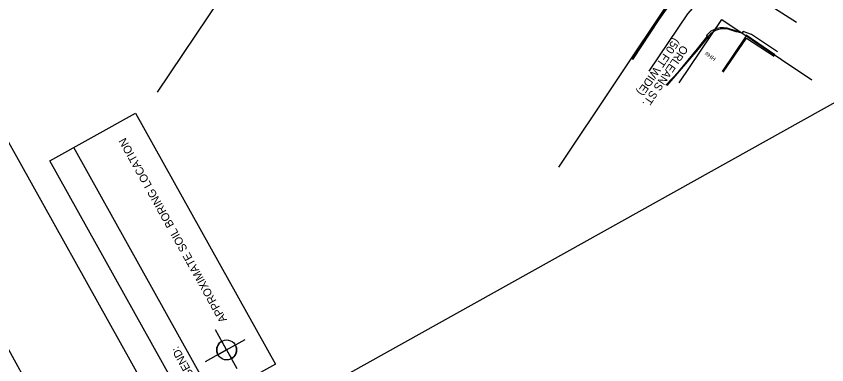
# Model space of a CAD drawing. Extents: x 13482447 to 13495412, y 324533 to 340229.
# Drawn here: x 13493140.7 to 13493623.3, y 331592.4 to 331799.7 of the extents above; entities that cross this region are included whole.
import ezdxf

# ---------------------------------------------------------------- set-up
doc = ezdxf.new("R2010")
doc.units = 0
for name, color, linetype in [('BORDER', 7, 'Continuous'), ('Default', 7, 'Continuous'), ('Level 1', 7, 'Continuous'), ('TYPICAL_TEXT_DIMEN_PR', 7, 'Continuous'), ('V-ANNO-TEXT', 7, 'Continuous'), ('V-BLDG-OTLN', 7, 'Continuous'), ('V-PROP-RWAY', 7, 'Continuous'), ('V-PVMT-BACK', 7, 'Continuous'), ('V-PVMT-CNTR', 7, 'Continuous'), ('V-PVMT-ROAD', 7, 'Continuous'), ('V-TOPO-IDEN', 7, 'Continuous')]:
    doc.layers.add(name, color=color, linetype=linetype)

msp = doc.modelspace()

# ---------------------------------------------------------------- linework, layer by layer
at = {"layer": 'Default'}
msp.add_lwpolyline([(13493738.83, 331810.18), (13493240.94, 331532.61)], dxfattribs=at)
at = {"layer": 'Level 1'}
for p, q in [((13493612.91, 330747.03), (13492913.2, 332001.03)), ((13493636.07, 330828.66), (13492994.84, 331977.87))]:
    msp.add_line(p, q, dxfattribs=at)
at = {"layer": 'TYPICAL_TEXT_DIMEN_PR'}
for p, q in [((13493258.89, 331571.46), (13493175.09, 331721.64)), ((13493265.99, 331601.22), (13493259.28, 331613.24)), ((13493265.99, 331601.22), (13493277, 331607.36)), ((13493265.99, 331601.22), (13493253.28, 331594.12)), ((13493265.99, 331601.22), (13493272.14, 331590.21))]:
    msp.add_line(p, q, dxfattribs=at)
msp.add_lwpolyline([(13493244.14, 331564.28), (13493160.79, 331713.66), (13493211.64, 331742.04), (13493295, 331592.65)], close=True, dxfattribs=at)
for points in [[(13493260.8, 331598.32), (13493265.99, 331601.22), (13493263.1, 331606.41)], [(13493271.18, 331604.11), (13493265.99, 331601.22), (13493268.89, 331596.03)]]:
    msp.add_lwpolyline(points, dxfattribs=at)
msp.add_circle((13493265.99, 331601.22), 5.94, dxfattribs=at)
for start, end in [(119.1605, 209.1605), (299.1605, 29.1605)]:
    msp.add_arc((13493265.99, 331601.22), 5.94, start, end, dxfattribs=at)
at = {"layer": 'V-BLDG-OTLN'}
for points in [[(13493592.42, 331776.73), (13493575.34, 331788.01), (13493561.02, 331766.8)], [(13493561.61, 331766.39), (13493575.55, 331786.74), (13493591.93, 331776)]]:
    msp.add_lwpolyline(points, dxfattribs=at)
at = {"layer": 'V-PROP-RWAY'}
for p, q in [((13493477.23, 332131.7), (13493224.66, 331754.53)), ((13493534, 331815.23), (13493463.52, 331709.94)), ((13493535.54, 331760.01), (13493560.86, 331797.83)), ((13493560.86, 331797.83), (13493614.45, 331761.96))]:
    msp.add_line(p, q, dxfattribs=at)
at = {"layer": 'V-PVMT-BACK'}
for points in [[(13493507.69, 331774.06), (13493523.14, 331797.99), (13493526.58, 331803.26), (13493531.99, 331810.53), (13493532.93, 331811.94), (13493533.5, 331813.14), (13493533.78, 331814.45), (13493533.73, 331815.79), (13493533.37, 331817.08), (13493532.71, 331818.25), (13493531.8, 331819.23), (13493531.23, 331819.64)], [(13493570.06, 331790.34), (13493569.44, 331790.51), (13493565.29, 331791.74), (13493564.57, 331791.94), (13493562.69, 331792.23), (13493560.79, 331792.2), (13493558.92, 331791.86), (13493557.13, 331791.21), (13493555.48, 331790.27), (13493554.01, 331789.06), (13493552.76, 331787.63), (13493552.7, 331787.55), (13493546.63, 331779.82), (13493528.01, 331758.48)]]:
    msp.add_lwpolyline(points, dxfattribs=at)
at = {"layer": 'V-PVMT-CNTR'}
for points in [[(13493605.37, 331796), (13493578.55, 331813.26), (13493565.46, 331822.12), (13493559.01, 331826.3), (13493554.28, 331829.11), (13493520.81, 331851.15), (13493485.5, 331874.76), (13493449.91, 331898.35), (13493414.95, 331921.85), (13493381.07, 331944.31), (13493362.78, 331957.08), (13493333.61, 331976.1), (13493307.04, 331993.94), (13493274.45, 332015.96), (13493240.12, 332038.89), (13493207.02, 332061.34), (13493179.15, 332079.98)], [(13493600.67, 331886.67), (13493578.69, 331854.34), (13493559.01, 331826.3), (13493547.8, 331809.65), (13493540.48, 331801.21), (13493517.42, 331767.01)]]:
    msp.add_lwpolyline(points, dxfattribs=at)
at = {"layer": 'V-PVMT-ROAD'}
for points in [[(13493507.76, 331774.02), (13493523.6, 331797.69), (13493533.24, 331811.64), (13493533.88, 331812.9), (13493534.22, 331814.27), (13493534.24, 331815.69), (13493533.95, 331817.07), (13493533.35, 331818.35), (13493532.48, 331819.46), (13493531.47, 331820.3), (13493512.48, 331832.85)], [(13493527.56, 331758.72), (13493535.27, 331766.85), (13493546.33, 331780.27), (13493552.34, 331787.82), (13493551.77, 331788.23), (13493553.03, 331789.7), (13493554.52, 331790.93), (13493556.19, 331791.91), (13493557.99, 331792.59), (13493559.89, 331792.97), (13493561.82, 331793.03), (13493563.73, 331792.78), (13493565.02, 331792.42), (13493570.19, 331790.8)], [(13493593.98, 331778.44), (13493578.57, 331788.84), (13493573.63, 331790.69), (13493572.83, 331789.68), (13493570.06, 331790.34)], [(13493592.47, 331776.83), (13493575.25, 331788.35)]]:
    msp.add_lwpolyline(points, dxfattribs=at)

# ---------------------------------------------------------------- texts
at = {"layer": 'BORDER'}
for s, p in [('APPROXIMATE SOIL BORING LOCATION', (13493266.31, 331619.14)), ('LEGEND:', (13493250.72, 331579.15))]:
    msp.add_text(s, height=4.8, rotation=119.1605, dxfattribs=at).set_placement(p)
at = {"layer": 'V-ANNO-TEXT'}
for s, p in [('(50 FT WIDE)', (13493532.36, 331787.17)), ('ORLEANS ST.', (13493537.16, 331782.88))]:
    msp.add_text(s, height=4.8, rotation=235.7802, dxfattribs=at).set_placement(p)
at = {"layer": 'V-TOPO-IDEN'}
msp.add_text('HH#', height=2.56, rotation=145.0433, dxfattribs=at).set_placement((13493557.66, 331774.89))

doc.saveas('drawing.dxf')
